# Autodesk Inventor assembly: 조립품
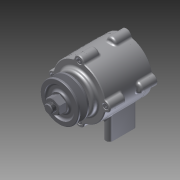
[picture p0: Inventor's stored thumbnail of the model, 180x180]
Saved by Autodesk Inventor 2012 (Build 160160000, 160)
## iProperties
Created: 2015-03
Part Number: 조립품
Document SubType Name: Assembly
Designer: user
Author: user
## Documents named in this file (11)
- C:\Users\user\Desktop\450306V1032\조립품.iam
- C:\Users\user\Desktop\450306V1032\본체.ipt
- C:\Users\user\Desktop\450306V1032\커버2.ipt
- C:\Users\user\Desktop\450306V1032\축.ipt
- C:\Users\user\Desktop\450306V1032\키(4 x 4 x 12).ipt
- C:\Users\user\Desktop\450306V1032\베어링 6204.ipt
- C:\Users\user\Desktop\450306V1032\커버.ipt
- C:\Users\user\Desktop\450306V1032\M 4 x 12.ipt
- C:\Users\user\Desktop\450306V1032\V벨트풀리.ipt
- C:\Users\user\Desktop\450306V1032\오일실.ipt
- C:\Users\user\Desktop\450306V1032\너트 M12x1.25.ipt
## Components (14 placed, 6 different names)
1. KS B 1311 (I) 4 x 4 x 12:1 — 각도:1, 각도:4
2. KS B 2023 6204 - 20 x 47 x 14:1
3. KS B 2023 6204 - 20 x 47 x 14:2
4. 그루브 풀리1:1 — 각도:4
5. KS B 2804 D D - 20 32 8:1
6. KS B 1012 클래스 1 일반 - 미터 M12x1.25:1 — 각도:5
7. KS B 1003 - 미터 M 4 x 12:1 — 각도:2
8. KS B 1003 - 미터 M 4 x 12:2 — 각도:3
9. KS B 1003 - 미터 M 4 x 12:3
10. KS B 1003 - 미터 M 4 x 12:4
11. KS B 1003 - 미터 M 4 x 12:5
12. KS B 1003 - 미터 M 4 x 12:6
13. KS B 1003 - 미터 M 4 x 12:7
14. KS B 1003 - 미터 M 4 x 12:8
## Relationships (5: Angle 5)
- 각도:1 [Angle]: KS B 1311 (I) 4 x 4 x 12:1
- 각도:2 [Angle]: KS B 1003 - 미터 M 4 x 12:1
- 각도:3 [Angle]: KS B 1003 - 미터 M 4 x 12:2
- 각도:4 [Angle]: KS B 1311 (I) 4 x 4 x 12:1 ↔ 그루브 풀리1:1
- 각도:5 [Angle]: KS B 1012 클래스 1 일반 - 미터 M12x1.25:1
